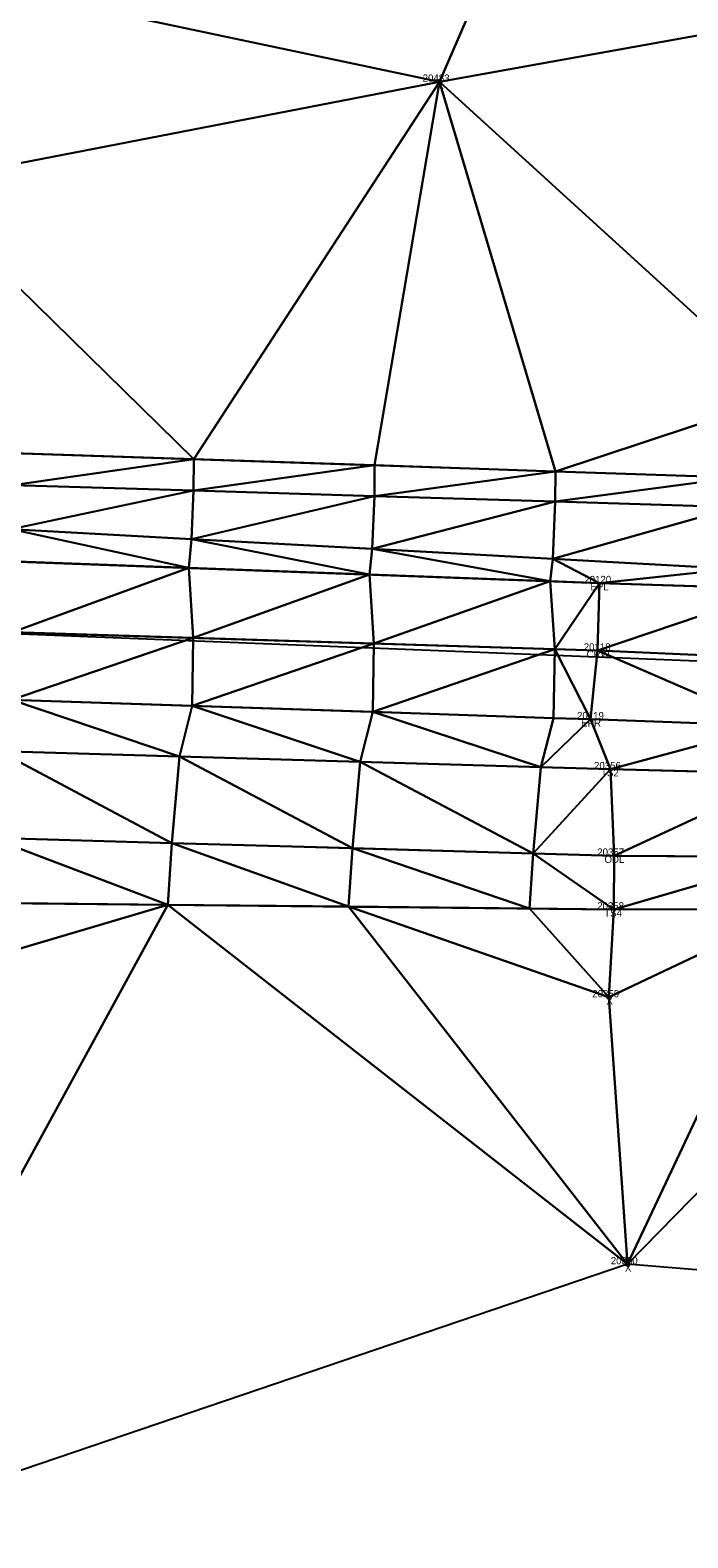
# Model space of a CAD drawing. Extents: x 1966740 to 1969291, y 1117379 to 1118460.
# Drawn here: x 1968240.1 to 1968331, y 1117801.2 to 1118009.8 of the extents above; entities that cross this region are included whole.
import ezdxf

# ---------------------------------------------------------------- set-up
doc = ezdxf.new("R2010")
doc.units = 0
for name, color, linetype in [('Level 1', 7, 'Continuous'), ('Level 3', 7, 'Continuous'), ('Level 30', 7, 'Continuous'), ('Level 35', 7, 'Continuous'), ('Level 50', 7, 'Continuous'), ('Level 52', 7, 'Continuous'), ('Level 53', 7, 'Continuous'), ('Level 56', 7, 'Continuous'), ('Level 6', 7, 'Continuous'), ('Level 62', 7, 'Continuous')]:
    doc.layers.add(name, color=color, linetype=linetype)

msp = doc.modelspace()

# ---------------------------------------------------------------- linework, layer by layer
at = {"layer": 'Level 1'}
msp.add_line((1968120.33, 1117930.94), (1969279.02, 1117884.95), dxfattribs=at)
at = {"layer": 'Level 3'}
for points in [[(1968106.63, 1117967.98), (1968158.56, 1117954.16), (1968212.75, 1117952.09), (1968371.01, 1117946.77)], [(1967874.77, 1117908.42), (1967879.51, 1117916.91), (1967881.27, 1117924.39), (1967885.24, 1117929.22), (1967913.7, 1117935.63), (1967966.11, 1117937.12), (1968012.39, 1117940.75), (1968059.42, 1117941.87), (1968105.44, 1117943.27), (1968158.32, 1117942.95), (1968212.48, 1117942.1), (1968371.25, 1117933.41), (1968422.85, 1117933.68), (1968531.49, 1117931.42)], [(1967878.98, 1117895.46), (1967875.66, 1117903.48), (1967919.49, 1117917.47), (1967966.4, 1117928.95), (1968012.66, 1117935.42), (1968058.94, 1117938.37), (1968105.99, 1117939.39), (1968158.7, 1117938.56), (1968212.05, 1117937.21), (1968318.79, 1117933.28), (1968422.76, 1117929.93), (1968530.54, 1117925.7)], [(1967878.98, 1117895.46), (1967922.07, 1117909.4), (1967968.89, 1117921.38), (1968013.49, 1117926.44), (1968059.29, 1117929.05), (1968105.63, 1117929.86), (1968159.12, 1117928.97), (1968212.65, 1117927.25), (1968318.5, 1117923.95), (1968422.42, 1117919.39), (1968529.36, 1117916.3)], [(1967878.98, 1117895.46), (1967883.11, 1117885.63), (1967924.99, 1117899.59), (1967970.68, 1117910.78), (1968014.42, 1117916.56), (1968059.13, 1117919.49), (1968105.39, 1117920.31), (1968159.16, 1117919.37), (1968212.5, 1117917.97), (1968317.55, 1117914.44), (1968421.52, 1117910.75), (1968527.82, 1117906.41)], [(1967884.1, 1117882.92), (1967891.06, 1117879.24), (1967898.84, 1117879.11), (1967924.17, 1117888.04), (1967954.33, 1117900.3), (1967970.81, 1117903.15), (1968012.93, 1117910.83), (1968059.62, 1117915.05), (1968105.25, 1117916.2), (1968157.57, 1117912.09), (1968210.74, 1117910.77), (1968320.32, 1117907.54), (1968423.18, 1117904.83), (1968528.99, 1117899.6)], [(1968058.02, 1117883.74), (1968104.17, 1117887.52), (1968156.67, 1117888.05), (1968209.1, 1117889.3), (1968320.79, 1117888.13), (1968422.17, 1117888.28), (1968528.68, 1117880.51)]]:
    msp.add_lwpolyline(points, dxfattribs=at)
at = {"layer": 'Level 30'}
for centre in [(1968296.69, 1118002.64), (1968320.08, 1117875.98), (1968322.64, 1117839.05)]:
    msp.add_circle(centre, 0.25, dxfattribs=at)
at = {"layer": 'Level 35'}
for points in [[(1968225.02, 1118017.79), (1968319.25, 1118054.83), (1968296.69, 1118002.64)], [(1968296.69, 1118002.64), (1968319.25, 1118054.83), (1968371.35, 1118016.1)], [(1968223.86, 1117988.51), (1968225.02, 1118017.79), (1968296.69, 1118002.64)], [(1968296.69, 1118002.64), (1968371.35, 1118016.1), (1968344.33, 1117959.2)], [(1968223.86, 1117988.51), (1968296.69, 1118002.64), (1968262.72, 1117950.41)], [(1968262.72, 1117950.41), (1968296.69, 1118002.64), (1968287.7, 1117949.57)], [(1968287.7, 1117949.57), (1968296.69, 1118002.64), (1968312.69, 1117948.73)], [(1968296.69, 1118002.64), (1968344.33, 1117959.2), (1968312.69, 1117948.73)], [(1968223.86, 1117988.51), (1968262.72, 1117950.41), (1968237.73, 1117951.25)], [(1968312.69, 1117948.73), (1968344.33, 1117959.2), (1968337.67, 1117947.89)], [(1968237.68, 1117946.84), (1968237.73, 1117951.25), (1968262.72, 1117950.41)], [(1968237.68, 1117946.84), (1968262.72, 1117950.41), (1968262.67, 1117946.08)], [(1968262.67, 1117946.08), (1968262.72, 1117950.41), (1968287.7, 1117949.57)], [(1968262.67, 1117946.08), (1968287.7, 1117949.57), (1968287.66, 1117945.32)], [(1968287.66, 1117945.32), (1968287.7, 1117949.57), (1968312.69, 1117948.73)], [(1968287.66, 1117945.32), (1968312.69, 1117948.73), (1968312.65, 1117944.55)], [(1968312.65, 1117944.55), (1968312.69, 1117948.73), (1968337.67, 1117947.89)], [(1968312.65, 1117944.55), (1968337.67, 1117947.89), (1968337.64, 1117943.79)], [(1968237.44, 1117940.74), (1968237.68, 1117946.84), (1968262.67, 1117946.08)], [(1968237.44, 1117940.74), (1968262.67, 1117946.08), (1968262.4, 1117939.37)], [(1968262.4, 1117939.37), (1968262.67, 1117946.08), (1968287.66, 1117945.32)], [(1968262.4, 1117939.37), (1968287.66, 1117945.32), (1968287.36, 1117938)], [(1968287.36, 1117938), (1968287.66, 1117945.32), (1968312.65, 1117944.55)], [(1968287.36, 1117938), (1968312.65, 1117944.55), (1968312.33, 1117936.64)], [(1968312.33, 1117936.64), (1968312.65, 1117944.55), (1968337.64, 1117943.79)], [(1968312.33, 1117936.64), (1968337.64, 1117943.79), (1968337.29, 1117935.27)], [(1968237.04, 1117936.29), (1968237.44, 1117940.74), (1968262.02, 1117935.37)], [(1968237.44, 1117940.74), (1968262.4, 1117939.37), (1968262.02, 1117935.37)], [(1968262.02, 1117935.37), (1968262.4, 1117939.37), (1968287, 1117934.45)], [(1968262.4, 1117939.37), (1968287.36, 1117938), (1968287, 1117934.45)], [(1968287, 1117934.45), (1968287.36, 1117938), (1968311.98, 1117933.54)], [(1968287.36, 1117938), (1968312.33, 1117936.64), (1968311.98, 1117933.54)], [(1968311.98, 1117933.54), (1968312.33, 1117936.64), (1968318.79, 1117933.28)], [(1968312.33, 1117936.64), (1968337.29, 1117935.27), (1968318.79, 1117933.28)], [(1968237.04, 1117936.29), (1968262.02, 1117935.37), (1968237.64, 1117926.47)], [(1968237.64, 1117926.47), (1968262.02, 1117935.37), (1968262.63, 1117925.69)], [(1968262.02, 1117935.37), (1968287, 1117934.45), (1968262.63, 1117925.69)], [(1968262.63, 1117925.69), (1968287, 1117934.45), (1968287.61, 1117924.91)], [(1968287, 1117934.45), (1968311.98, 1117933.54), (1968287.61, 1117924.91)], [(1968318.79, 1117933.28), (1968337.29, 1117935.27), (1968343.78, 1117932.48)], [(1968287.61, 1117924.91), (1968311.98, 1117933.54), (1968312.6, 1117924.13)], [(1968311.98, 1117933.54), (1968318.79, 1117933.28), (1968312.6, 1117924.13)], [(1968312.6, 1117924.13), (1968318.79, 1117933.28), (1968318.5, 1117923.95)], [(1968318.5, 1117923.95), (1968318.79, 1117933.28), (1968343.78, 1117932.48)], [(1968318.5, 1117923.95), (1968343.78, 1117932.48), (1968343.48, 1117922.85)], [(1968237.49, 1117917.13), (1968237.64, 1117926.47), (1968262.63, 1117925.69)], [(1968237.49, 1117917.13), (1968262.63, 1117925.69), (1968262.47, 1117916.29)], [(1968262.47, 1117916.29), (1968262.63, 1117925.69), (1968287.61, 1117924.91)], [(1968262.47, 1117916.29), (1968287.61, 1117924.91), (1968287.46, 1117915.45)], [(1968287.46, 1117915.45), (1968287.61, 1117924.91), (1968312.6, 1117924.13)], [(1968287.46, 1117915.45), (1968312.6, 1117924.13), (1968312.44, 1117914.61)], [(1968312.44, 1117914.61), (1968312.6, 1117924.13), (1968317.55, 1117914.44)], [(1968312.6, 1117924.13), (1968318.5, 1117923.95), (1968317.55, 1117914.44)], [(1968317.55, 1117914.44), (1968318.5, 1117923.95), (1968342.53, 1117913.55)], [(1968318.5, 1117923.95), (1968343.48, 1117922.85), (1968342.53, 1117913.55)], [(1968235.73, 1117910.04), (1968237.49, 1117917.13), (1968260.72, 1117909.3)], [(1968237.49, 1117917.13), (1968262.47, 1117916.29), (1968260.72, 1117909.3)], [(1968260.72, 1117909.3), (1968262.47, 1117916.29), (1968285.71, 1117908.56)], [(1968262.47, 1117916.29), (1968287.46, 1117915.45), (1968285.71, 1117908.56)], [(1968285.71, 1117908.56), (1968287.46, 1117915.45), (1968310.7, 1117907.82)], [(1968287.46, 1117915.45), (1968312.44, 1117914.61), (1968310.7, 1117907.82)], [(1968310.7, 1117907.82), (1968312.44, 1117914.61), (1968317.55, 1117914.44)], [(1968310.7, 1117907.82), (1968317.55, 1117914.44), (1968320.32, 1117907.54)], [(1968317.55, 1117914.44), (1968342.53, 1117913.55), (1968320.32, 1117907.54)], [(1968320.32, 1117907.54), (1968342.53, 1117913.55), (1968345.31, 1117906.88)], [(1968234.65, 1117898.04), (1968235.73, 1117910.04), (1968259.64, 1117897.32)], [(1968235.73, 1117910.04), (1968260.72, 1117909.3), (1968259.64, 1117897.32)], [(1968259.64, 1117897.32), (1968260.72, 1117909.3), (1968284.63, 1117896.61)], [(1968260.72, 1117909.3), (1968285.71, 1117908.56), (1968284.63, 1117896.61)], [(1968284.63, 1117896.61), (1968285.71, 1117908.56), (1968309.62, 1117895.89)], [(1968285.71, 1117908.56), (1968310.7, 1117907.82), (1968309.62, 1117895.89)], [(1968309.62, 1117895.89), (1968310.7, 1117907.82), (1968320.32, 1117907.54)], [(1968309.62, 1117895.89), (1968320.32, 1117907.54), (1968320.81, 1117895.57)], [(1968320.32, 1117907.54), (1968345.31, 1117906.88), (1968320.81, 1117895.57)], [(1968320.81, 1117895.57), (1968345.31, 1117906.88), (1968345.8, 1117895.41)], [(1968234.1, 1117889.04), (1968234.65, 1117898.04), (1968259.1, 1117888.78)], [(1968234.65, 1117898.04), (1968259.64, 1117897.32), (1968259.1, 1117888.78)], [(1968259.1, 1117888.78), (1968259.64, 1117897.32), (1968284.09, 1117888.52)], [(1968259.64, 1117897.32), (1968284.63, 1117896.61), (1968284.09, 1117888.52)], [(1968284.09, 1117888.52), (1968284.63, 1117896.61), (1968309.09, 1117888.25)], [(1968284.63, 1117896.61), (1968309.62, 1117895.89), (1968309.09, 1117888.25)], [(1968309.09, 1117888.25), (1968309.62, 1117895.89), (1968320.79, 1117888.13)], [(1968309.62, 1117895.89), (1968320.81, 1117895.57), (1968320.79, 1117888.13)], [(1968320.79, 1117888.13), (1968320.81, 1117895.57), (1968345.8, 1117895.41)], [(1968320.79, 1117888.13), (1968345.8, 1117895.41), (1968345.79, 1117888.17)], [(1968211.33, 1117801.21), (1968214.22, 1117875.48), (1968259.1, 1117888.78)], [(1968211.33, 1117801.21), (1968259.1, 1117888.78), (1968322.64, 1117839.05)], [(1968214.22, 1117875.48), (1968234.1, 1117889.04), (1968259.1, 1117888.78)], [(1968259.1, 1117888.78), (1968284.09, 1117888.52), (1968322.64, 1117839.05)], [(1968284.09, 1117888.52), (1968309.09, 1117888.25), (1968320.08, 1117875.98)], [(1968284.09, 1117888.52), (1968320.08, 1117875.98), (1968322.64, 1117839.05)], [(1968309.09, 1117888.25), (1968320.79, 1117888.13), (1968320.08, 1117875.98)], [(1968320.08, 1117875.98), (1968320.79, 1117888.13), (1968345.79, 1117888.17)], [(1968320.08, 1117875.98), (1968345.79, 1117888.17), (1968322.64, 1117839.05)], [(1968322.64, 1117839.05), (1968345.79, 1117888.17), (1968370.79, 1117888.2)], [(1968322.64, 1117839.05), (1968370.79, 1117888.2), (1968423.45, 1117830.77)]]:
    msp.add_lwpolyline(points, close=True, dxfattribs=at)
at = {"layer": 'Level 50'}
for centre in [(1968318.79, 1117933.28), (1968318.5, 1117923.95), (1968317.55, 1117914.44), (1968320.32, 1117907.54), (1968320.81, 1117895.57), (1968320.79, 1117888.13)]:
    msp.add_circle(centre, 0.001, dxfattribs=at)
at = {"layer": 'Level 6'}
for points in [[(1968105.42, 1117949), (1968158.12, 1117948.98), (1968212.69, 1117947.6), (1968364.14, 1117942.98)], [(1967868.28, 1117817.14), (1967892.54, 1117814.5), (1967928.24, 1117834.22), (1967973.92, 1117854.29), (1967982.67, 1117861.15), (1968021.78, 1117883.3), (1968056.97, 1117897.44), (1968105.42, 1117898.77), (1968155.9, 1117899.84), (1968209.66, 1117898.76), (1968320.81, 1117895.57), (1968422.79, 1117894.92), (1968528.55, 1117888.35)]]:
    msp.add_lwpolyline(points, dxfattribs=at)

# ---------------------------------------------------------------- texts
at = {"layer": 'Level 52'}
for s, p in [('20483', (1968294.34, 1118002.64)), ('20359', (1968317.79, 1117875.98)), ('20360', (1968320.35, 1117839.05))]:
    msp.add_text(s, height=1, dxfattribs=at).set_placement(p)
at = {"layer": 'Level 53'}
for s, p in [('20120', (1968316.69, 1117933.28)), ('EPL', (1968317.53, 1117932.28)), ('20118', (1968316.61, 1117923.95)), ('CRW', (1968317.01, 1117922.95)), ('20119', (1968315.68, 1117914.44)), ('EPR', (1968316.25, 1117913.44)), ('20356', (1968318.03, 1117907.54)), ('TS2', (1968319, 1117906.54)), ('20358', (1968318.47, 1117888.13)), ('TS4', (1968319.44, 1117887.13))]:
    msp.add_text(s, height=1, dxfattribs=at).set_placement(p)
at = {"layer": 'Level 56'}
for s, p in [('20357', (1968318.48, 1117895.57)), ('ODL', (1968319.48, 1117894.57))]:
    msp.add_text(s, height=1, dxfattribs=at).set_placement(p)
at = {"layer": 'Level 62'}
for p in [(1968296.35, 1118001.64), (1968319.75, 1117874.98), (1968322.31, 1117838.05)]:
    msp.add_text('X', height=1, dxfattribs=at).set_placement(p)

doc.saveas('drawing.dxf')
